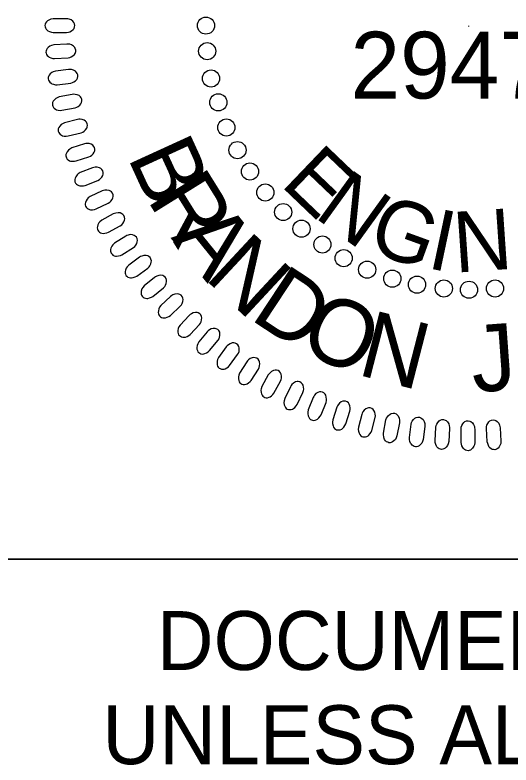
# Model space of a CAD drawing. Extents: x 505602 to 507286, y 483109 to 484209.
# Drawn here: x 507076.9 to 507123.2, y 484026.9 to 484097 of the extents above; entities that cross this region are included whole.
import ezdxf

# ---------------------------------------------------------------- set-up
doc = ezdxf.new("R2010")
doc.units = 0
for name, color, linetype in [('Sheet PE Seal Cell', 7, 'Continuous'), ('Sheet Profile CELL', 7, 'Continuous'), ('Sheet Sticker Exception Certification CELL', 7, 'Continuous')]:
    doc.layers.add(name, color=color, linetype=linetype)

msp = doc.modelspace()

# ---------------------------------------------------------------- linework, layer by layer
at = {"layer": 'Sheet PE Seal Cell'}
msp.add_line((507119.206, 484095.991), (507119.206, 484095.944), dxfattribs=at)
for points in [[(507081.659, 484096.654), (507080.432, 484096.654), (507080.213, 484096.616), (507080.073, 484096.565), (507079.904, 484096.453), (507079.794, 484096.355), (507079.714, 484096.243), (507079.674, 484096.139), (507079.654, 484096.026), (507079.674, 484095.915), (507079.704, 484095.795), (507079.763, 484095.69), (507079.864, 484095.586), (507079.943, 484095.526), (507080.093, 484095.458), (507080.273, 484095.399), (507080.432, 484095.376), (507081.689, 484095.368), (507081.858, 484095.39), (507081.998, 484095.436), (507082.157, 484095.525), (507082.297, 484095.637), (507082.377, 484095.734), (507082.437, 484095.891), (507082.457, 484096.041), (507082.416, 484096.19), (507082.367, 484096.295), (507082.268, 484096.422), (507082.098, 484096.542), (507081.918, 484096.609), (507081.789, 484096.639)], [(507081.712, 484094.296), (507080.487, 484094.22), (507080.271, 484094.169), (507080.134, 484094.108), (507079.972, 484093.985), (507079.868, 484093.881), (507079.796, 484093.764), (507079.763, 484093.658), (507079.75, 484093.544), (507079.777, 484093.434), (507079.815, 484093.316), (507079.88, 484093.216), (507079.987, 484093.117), (507080.07, 484093.063), (507080.223, 484093.005), (507080.406, 484092.956), (507080.566, 484092.944), (507081.822, 484093.015), (507081.99, 484093.048), (507082.126, 484093.102), (507082.279, 484093.202), (507082.412, 484093.322), (507082.486, 484093.423), (507082.536, 484093.584), (507082.546, 484093.734), (507082.497, 484093.881), (507082.44, 484093.983), (507082.333, 484094.103), (507082.157, 484094.212), (507081.973, 484094.268), (507081.842, 484094.29)], [(507081.876, 484091.915), (507080.659, 484091.762), (507080.446, 484091.697), (507080.314, 484091.628), (507080.16, 484091.496), (507080.063, 484091.385), (507079.998, 484091.264), (507079.972, 484091.155), (507079.966, 484091.041), (507080, 484090.933), (507080.044, 484090.818), (507080.116, 484090.721), (507080.229, 484090.63), (507080.316, 484090.581), (507080.472, 484090.533), (507080.658, 484090.496), (507080.819, 484090.494), (507082.067, 484090.643), (507082.232, 484090.686), (507082.365, 484090.749), (507082.512, 484090.857), (507082.636, 484090.986), (507082.704, 484091.092), (507082.743, 484091.256), (507082.744, 484091.407), (507082.686, 484091.55), (507082.623, 484091.648), (507082.509, 484091.762), (507082.326, 484091.859), (507082.139, 484091.903), (507082.007, 484091.916)], [(507082.21, 484089.59), (507081.004, 484089.36), (507080.796, 484089.282), (507080.669, 484089.206), (507080.523, 484089.063), (507080.433, 484088.947), (507080.376, 484088.822), (507080.356, 484088.712), (507080.358, 484088.598), (507080.398, 484088.492), (507080.45, 484088.38), (507080.528, 484088.288), (507080.646, 484088.204), (507080.735, 484088.16), (507080.895, 484088.122), (507081.083, 484088.097), (507081.243, 484088.104), (507082.479, 484088.332), (507082.642, 484088.386), (507082.771, 484088.456), (507082.91, 484088.574), (507083.027, 484088.711), (507083.087, 484088.821), (507083.116, 484088.986), (507083.108, 484089.137), (507083.041, 484089.276), (507082.972, 484089.37), (507082.85, 484089.476), (507082.662, 484089.561), (507082.472, 484089.594), (507082.34, 484089.599)], [(507082.689, 484087.249), (507081.501, 484086.944), (507081.298, 484086.853), (507081.175, 484086.768), (507081.039, 484086.617), (507080.957, 484086.496), (507080.907, 484086.367), (507080.895, 484086.256), (507080.903, 484086.142), (507080.95, 484086.039), (507081.009, 484085.931), (507081.093, 484085.844), (507081.216, 484085.767), (507081.308, 484085.729), (507081.469, 484085.701), (507081.658, 484085.688), (507081.818, 484085.706), (507083.037, 484086.01), (507083.196, 484086.074), (507083.32, 484086.153), (507083.452, 484086.279), (507083.56, 484086.422), (507083.613, 484086.536), (507083.632, 484086.703), (507083.614, 484086.853), (507083.538, 484086.988), (507083.464, 484087.077), (507083.336, 484087.176), (507083.142, 484087.249), (507082.951, 484087.27), (507082.818, 484087.266)], [(507083.343, 484084.965), (507082.176, 484084.586), (507081.979, 484084.483), (507081.862, 484084.391), (507081.735, 484084.231), (507081.661, 484084.104), (507081.62, 484083.973), (507081.615, 484083.862), (507081.63, 484083.749), (507081.684, 484083.649), (507081.749, 484083.544), (507081.838, 484083.463), (507081.966, 484083.395), (507082.059, 484083.361), (507082.223, 484083.344), (507082.412, 484083.343), (507082.571, 484083.37), (507083.768, 484083.751), (507083.922, 484083.825), (507084.042, 484083.911), (507084.165, 484084.045), (507084.263, 484084.195), (507084.31, 484084.312), (507084.318, 484084.48), (507084.291, 484084.628), (507084.207, 484084.758), (507084.127, 484084.842), (507083.993, 484084.932), (507083.795, 484084.994), (507083.603, 484085.002), (507083.471, 484084.99)], [(507084.102, 484082.727), (507082.961, 484082.277), (507082.77, 484082.161), (507082.659, 484082.061), (507082.543, 484081.894), (507082.477, 484081.763), (507082.444, 484081.63), (507082.446, 484081.518), (507082.468, 484081.406), (507082.528, 484081.31), (507082.6, 484081.209), (507082.693, 484081.134), (507082.825, 484081.074), (507082.921, 484081.047), (507083.086, 484081.04), (507083.274, 484081.05), (507083.431, 484081.088), (507084.602, 484081.543), (507084.752, 484081.626), (507084.865, 484081.719), (507084.98, 484081.861), (507085.069, 484082.017), (507085.108, 484082.137), (507085.105, 484082.305), (507085.069, 484082.452), (507084.977, 484082.575), (507084.892, 484082.654), (507084.753, 484082.736), (507084.551, 484082.784), (507084.359, 484082.781), (507084.228, 484082.761)], [(507085.001, 484080.568), (507083.891, 484080.046), (507083.709, 484079.919), (507083.604, 484079.812), (507083.499, 484079.638), (507083.441, 484079.504), (507083.416, 484079.368), (507083.425, 484079.257), (507083.454, 484079.147), (507083.52, 484079.054), (507083.598, 484078.958), (507083.697, 484078.889), (507083.832, 484078.837), (507083.929, 484078.817), (507084.093, 484078.819), (507084.281, 484078.842), (507084.435, 484078.889), (507085.576, 484079.417), (507085.719, 484079.51), (507085.827, 484079.61), (507085.932, 484079.758), (507086.012, 484079.919), (507086.043, 484080.042), (507086.03, 484080.209), (507085.984, 484080.353), (507085.884, 484080.471), (507085.794, 484080.545), (507085.651, 484080.618), (507085.446, 484080.653), (507085.255, 484080.638), (507085.125, 484080.61)], [(507086.049, 484078.419), (507084.973, 484077.829), (507084.799, 484077.691), (507084.702, 484077.577), (507084.607, 484077.398), (507084.558, 484077.259), (507084.542, 484077.123), (507084.557, 484077.012), (507084.594, 484076.904), (507084.666, 484076.816), (507084.75, 484076.725), (507084.852, 484076.662), (507084.99, 484076.619), (507085.089, 484076.604), (507085.252, 484076.617), (507085.438, 484076.652), (507085.589, 484076.708), (507086.694, 484077.307), (507086.832, 484077.409), (507086.932, 484077.515), (507087.029, 484077.67), (507087.097, 484077.835), (507087.121, 484077.96), (507087.097, 484078.126), (507087.043, 484078.267), (507086.936, 484078.378), (507086.842, 484078.446), (507086.693, 484078.509), (507086.487, 484078.532), (507086.297, 484078.505), (507086.169, 484078.469)], [(507087.205, 484076.345), (507086.169, 484075.687), (507086.003, 484075.539), (507085.914, 484075.42), (507085.83, 484075.234), (507085.79, 484075.094), (507085.783, 484074.956), (507085.805, 484074.846), (507085.848, 484074.741), (507085.926, 484074.657), (507086.015, 484074.572), (507086.121, 484074.516), (507086.261, 484074.481), (507086.36, 484074.473), (507086.523, 484074.496), (507086.707, 484074.542), (507086.853, 484074.608), (507087.919, 484075.275), (507088.05, 484075.384), (507088.144, 484075.498), (507088.23, 484075.658), (507088.288, 484075.828), (507088.304, 484075.953), (507088.27, 484076.118), (507088.207, 484076.255), (507088.093, 484076.359), (507087.995, 484076.421), (507087.842, 484076.475), (507087.635, 484076.485), (507087.447, 484076.446), (507087.322, 484076.401)], [(507088.482, 484074.37), (507087.488, 484073.649), (507087.333, 484073.49), (507087.25, 484073.366), (507087.179, 484073.175), (507087.148, 484073.032), (507087.149, 484072.894), (507087.178, 484072.787), (507087.228, 484072.683), (507087.31, 484072.605), (507087.405, 484072.526), (507087.515, 484072.476), (507087.657, 484072.45), (507087.756, 484072.449), (507087.917, 484072.482), (507088.097, 484072.539), (507088.24, 484072.614), (507089.261, 484073.347), (507089.385, 484073.465), (507089.471, 484073.583), (507089.548, 484073.749), (507089.595, 484073.922), (507089.603, 484074.047), (507089.559, 484074.21), (507089.487, 484074.343), (507089.367, 484074.44), (507089.265, 484074.495), (507089.11, 484074.54), (507088.903, 484074.537), (507088.717, 484074.486), (507088.595, 484074.434)], [(507089.885, 484072.488), (507088.939, 484071.706), (507088.794, 484071.538), (507088.72, 484071.409), (507088.661, 484071.215), (507088.638, 484071.07), (507088.648, 484070.933), (507088.684, 484070.827), (507088.74, 484070.727), (507088.827, 484070.654), (507088.926, 484070.581), (507089.039, 484070.538), (507089.182, 484070.521), (507089.282, 484070.526), (507089.44, 484070.569), (507089.616, 484070.638), (507089.754, 484070.721), (507090.727, 484071.517), (507090.844, 484071.642), (507090.922, 484071.766), (507090.988, 484071.936), (507091.025, 484072.112), (507091.024, 484072.237), (507090.97, 484072.397), (507090.89, 484072.524), (507090.764, 484072.614), (507090.659, 484072.663), (507090.501, 484072.698), (507090.295, 484072.682), (507090.113, 484072.619), (507089.994, 484072.56)], [(507091.395, 484070.718), (507090.5, 484069.878), (507090.366, 484069.701), (507090.3, 484069.568), (507090.253, 484069.37), (507090.24, 484069.224), (507090.258, 484069.087), (507090.301, 484068.983), (507090.363, 484068.888), (507090.454, 484068.82), (507090.558, 484068.753), (507090.673, 484068.718), (507090.818, 484068.71), (507090.916, 484068.721), (507091.072, 484068.774), (507091.244, 484068.853), (507091.375, 484068.946), (507092.296, 484069.801), (507092.405, 484069.933), (507092.476, 484070.062), (507092.531, 484070.236), (507092.556, 484070.413), (507092.548, 484070.538), (507092.484, 484070.695), (507092.396, 484070.817), (507092.265, 484070.898), (507092.157, 484070.941), (507091.997, 484070.965), (507091.792, 484070.936), (507091.614, 484070.862), (507091.5, 484070.795)], [(507093.131, 484068.94), (507092.29, 484068.045), (507092.167, 484067.86), (507092.11, 484067.723), (507092.075, 484067.522), (507092.071, 484067.375), (507092.098, 484067.241), (507092.147, 484067.141), (507092.215, 484067.049), (507092.31, 484066.987), (507092.419, 484066.927), (507092.535, 484066.898), (507092.68, 484066.9), (507092.778, 484066.916), (507092.93, 484066.979), (507093.096, 484067.069), (507093.222, 484067.17), (507094.088, 484068.081), (507094.187, 484068.22), (507094.25, 484068.353), (507094.294, 484068.53), (507094.308, 484068.708), (507094.292, 484068.833), (507094.219, 484068.984), (507094.123, 484069.102), (507093.987, 484069.174), (507093.876, 484069.21), (507093.716, 484069.225), (507093.513, 484069.182), (507093.34, 484069.098), (507093.23, 484069.024)], [(507094.821, 484067.41), (507094.038, 484066.464), (507093.927, 484066.271), (507093.878, 484066.131), (507093.856, 484065.929), (507093.862, 484065.782), (507093.897, 484065.649), (507093.952, 484065.551), (507094.026, 484065.464), (507094.124, 484065.409), (507094.236, 484065.356), (507094.354, 484065.335), (507094.499, 484065.345), (507094.596, 484065.368), (507094.743, 484065.44), (507094.903, 484065.54), (507095.023, 484065.649), (507095.83, 484066.613), (507095.921, 484066.757), (507095.974, 484066.894), (507096.008, 484067.073), (507096.011, 484067.252), (507095.986, 484067.377), (507095.903, 484067.522), (507095.801, 484067.633), (507095.661, 484067.697), (507095.547, 484067.726), (507095.386, 484067.73), (507095.187, 484067.676), (507095.019, 484067.58), (507094.914, 484067.5)], [(507096.601, 484066.009), (507095.88, 484065.016), (507095.781, 484064.817), (507095.741, 484064.673), (507095.732, 484064.47), (507095.747, 484064.324), (507095.79, 484064.194), (507095.851, 484064.1), (507095.93, 484064.018), (507096.033, 484063.968), (507096.148, 484063.922), (507096.267, 484063.909), (507096.41, 484063.928), (507096.506, 484063.957), (507096.648, 484064.039), (507096.802, 484064.149), (507096.914, 484064.264), (507097.659, 484065.277), (507097.74, 484065.427), (507097.786, 484065.567), (507097.808, 484065.748), (507097.8, 484065.927), (507097.767, 484066.048), (507097.676, 484066.19), (507097.566, 484066.294), (507097.422, 484066.349), (507097.308, 484066.37), (507097.147, 484066.365), (507096.95, 484066.297), (507096.79, 484066.192), (507096.69, 484066.104)], [(507098.503, 484064.596), (507097.846, 484063.56), (507097.759, 484063.355), (507097.728, 484063.209), (507097.732, 484063.005), (507097.756, 484062.861), (507097.808, 484062.734), (507097.874, 484062.643), (507097.959, 484062.567), (507098.063, 484062.523), (507098.181, 484062.484), (507098.301, 484062.479), (507098.443, 484062.507), (507098.536, 484062.543), (507098.673, 484062.632), (507098.82, 484062.752), (507098.924, 484062.875), (507099.604, 484063.931), (507099.676, 484064.087), (507099.713, 484064.229), (507099.723, 484064.411), (507099.703, 484064.589), (507099.663, 484064.709), (507099.564, 484064.844), (507099.448, 484064.94), (507099.3, 484064.987), (507099.185, 484065.001), (507099.025, 484064.985), (507098.833, 484064.906), (507098.679, 484064.79), (507098.585, 484064.697)], [(507100.521, 484063.38), (507099.93, 484062.305), (507099.857, 484062.095), (507099.835, 484061.948), (507099.852, 484061.745), (507099.884, 484061.602), (507099.944, 484061.478), (507100.016, 484061.392), (507100.105, 484061.321), (507100.212, 484061.285), (507100.332, 484061.253), (507100.452, 484061.255), (507100.592, 484061.292), (507100.683, 484061.333), (507100.814, 484061.432), (507100.953, 484061.56), (507101.05, 484061.689), (507101.662, 484062.787), (507101.723, 484062.946), (507101.751, 484063.09), (507101.75, 484063.273), (507101.72, 484063.449), (507101.673, 484063.566), (507101.564, 484063.694), (507101.442, 484063.784), (507101.292, 484063.821), (507101.176, 484063.828), (507101.017, 484063.802), (507100.831, 484063.71), (507100.685, 484063.586), (507100.596, 484063.487)], [(507102.58, 484062.274), (507102.058, 484061.164), (507101.998, 484060.95), (507101.986, 484060.801), (507102.015, 484060.599), (507102.056, 484060.459), (507102.124, 484060.339), (507102.201, 484060.258), (507102.295, 484060.193), (507102.404, 484060.163), (507102.525, 484060.139), (507102.645, 484060.148), (507102.783, 484060.194), (507102.871, 484060.241), (507102.995, 484060.347), (507103.126, 484060.484), (507103.215, 484060.619), (507103.757, 484061.753), (507103.808, 484061.916), (507103.827, 484062.061), (507103.814, 484062.244), (507103.773, 484062.418), (507103.718, 484062.532), (507103.602, 484062.652), (507103.474, 484062.735), (507103.323, 484062.762), (507103.206, 484062.761), (507103.049, 484062.726), (507102.869, 484062.623), (507102.732, 484062.489), (507102.65, 484062.385)], [(507104.708, 484061.266), (507104.256, 484060.125), (507104.21, 484059.907), (507104.207, 484059.758), (507104.249, 484059.559), (507104.298, 484059.421), (507104.374, 484059.306), (507104.456, 484059.23), (507104.553, 484059.17), (507104.664, 484059.148), (507104.787, 484059.132), (507104.906, 484059.148), (507105.04, 484059.203), (507105.125, 484059.255), (507105.243, 484059.369), (507105.364, 484059.514), (507105.444, 484059.654), (507105.914, 484060.82), (507105.956, 484060.985), (507105.965, 484061.131), (507105.941, 484061.313), (507105.888, 484061.484), (507105.827, 484061.594), (507105.703, 484061.708), (507105.571, 484061.781), (507105.418, 484061.799), (507105.302, 484061.791), (507105.147, 484061.746), (507104.974, 484061.632), (507104.845, 484061.489), (507104.77, 484061.38)], [(507106.917, 484060.363), (507106.537, 484059.197), (507106.505, 484058.976), (507106.511, 484058.828), (507106.565, 484058.631), (507106.624, 484058.497), (507106.706, 484058.387), (507106.793, 484058.317), (507106.894, 484058.263), (507107.006, 484058.247), (507107.13, 484058.239), (507107.247, 484058.263), (507107.378, 484058.326), (507107.459, 484058.383), (507107.57, 484058.505), (507107.682, 484058.657), (507107.753, 484058.801), (507108.149, 484059.994), (507108.18, 484060.162), (507108.18, 484060.309), (507108.144, 484060.488), (507108.081, 484060.655), (507108.013, 484060.762), (507107.882, 484060.867), (507107.746, 484060.932), (507107.592, 484060.941), (507107.477, 484060.925), (507107.325, 484060.87), (507107.159, 484060.746), (507107.039, 484060.596), (507106.971, 484060.482)], [(507109.25, 484059.69), (507108.944, 484058.502), (507108.926, 484058.281), (507108.941, 484058.132), (507109.008, 484057.94), (507109.074, 484057.809), (507109.164, 484057.705), (507109.255, 484057.64), (507109.358, 484057.592), (507109.472, 484057.584), (507109.595, 484057.584), (507109.711, 484057.615), (507109.837, 484057.686), (507109.915, 484057.747), (507110.018, 484057.876), (507110.12, 484058.035), (507110.182, 484058.184), (507110.502, 484059.399), (507110.522, 484059.569), (507110.513, 484059.715), (507110.466, 484059.892), (507110.393, 484060.055), (507110.318, 484060.157), (507110.181, 484060.254), (507110.042, 484060.31), (507109.886, 484060.309), (507109.773, 484060.287), (507109.625, 484060.222), (507109.467, 484060.087), (507109.357, 484059.93), (507109.296, 484059.812)], [(507112.772, 484058.903), (507112.541, 484057.698), (507112.463, 484057.489), (507112.386, 484057.362), (507112.244, 484057.216), (507112.128, 484057.127), (507112.003, 484057.07), (507111.892, 484057.05), (507111.778, 484057.052), (507111.673, 484057.092), (507111.56, 484057.144), (507111.469, 484057.222), (507111.385, 484057.34), (507111.341, 484057.43), (507111.303, 484057.589), (507111.278, 484057.777), (507111.286, 484057.938), (507111.514, 484059.173), (507111.568, 484059.336), (507111.639, 484059.464), (507111.757, 484059.604), (507111.893, 484059.72), (507112.003, 484059.781), (507112.168, 484059.81), (507112.32, 484059.801), (507112.458, 484059.734), (507112.552, 484059.665), (507112.658, 484059.544), (507112.743, 484059.355), (507112.776, 484059.165), (507112.781, 484059.033)], [(507115.138, 484058.577), (507114.983, 484057.36), (507114.919, 484057.147), (507114.849, 484057.014), (507114.717, 484056.86), (507114.607, 484056.764), (507114.485, 484056.698), (507114.377, 484056.672), (507114.263, 484056.667), (507114.155, 484056.701), (507114.039, 484056.745), (507113.943, 484056.817), (507113.852, 484056.93), (507113.802, 484057.017), (507113.754, 484057.174), (507113.718, 484057.359), (507113.715, 484057.52), (507113.866, 484058.767), (507113.909, 484058.933), (507113.972, 484059.066), (507114.08, 484059.213), (507114.209, 484059.338), (507114.316, 484059.404), (507114.479, 484059.444), (507114.63, 484059.445), (507114.773, 484059.386), (507114.871, 484059.324), (507114.985, 484059.209), (507115.081, 484059.026), (507115.126, 484058.839), (507115.139, 484058.707)], [(507117.455, 484058.379), (507117.377, 484057.155), (507117.326, 484056.939), (507117.265, 484056.802), (507117.143, 484056.64), (507117.039, 484056.536), (507116.922, 484056.464), (507116.815, 484056.43), (507116.701, 484056.418), (507116.591, 484056.446), (507116.474, 484056.482), (507116.373, 484056.548), (507116.275, 484056.655), (507116.22, 484056.738), (507116.162, 484056.892), (507116.114, 484057.075), (507116.102, 484057.236), (507116.173, 484058.49), (507116.207, 484058.658), (507116.261, 484058.794), (507116.36, 484058.948), (507116.48, 484059.08), (507116.583, 484059.154), (507116.743, 484059.203), (507116.894, 484059.214), (507117.041, 484059.164), (507117.141, 484059.108), (507117.262, 484059.001), (507117.37, 484058.824), (507117.427, 484058.64), (507117.448, 484058.51)], [(507119.808, 484058.307), (507119.808, 484057.08), (507119.77, 484056.862), (507119.718, 484056.721), (507119.606, 484056.552), (507119.508, 484056.442), (507119.396, 484056.362), (507119.292, 484056.323), (507119.18, 484056.303), (507119.068, 484056.323), (507118.948, 484056.353), (507118.843, 484056.412), (507118.738, 484056.513), (507118.679, 484056.592), (507118.611, 484056.742), (507118.552, 484056.921), (507118.529, 484057.081), (507118.522, 484058.337), (507118.545, 484058.507), (507118.59, 484058.647), (507118.679, 484058.806), (507118.791, 484058.946), (507118.889, 484059.026), (507119.046, 484059.085), (507119.196, 484059.105), (507119.345, 484059.065), (507119.45, 484059.015), (507119.577, 484058.916), (507119.696, 484058.746), (507119.764, 484058.566), (507119.793, 484058.437)], [(507122.175, 484058.43), (507122.251, 484057.205), (507122.228, 484056.984), (507122.185, 484056.841), (507122.083, 484056.665), (507121.994, 484056.549), (507121.886, 484056.463), (507121.785, 484056.417), (507121.674, 484056.39), (507121.561, 484056.403), (507121.44, 484056.425), (507121.331, 484056.478), (507121.22, 484056.572), (507121.156, 484056.647), (507121.08, 484056.793), (507121.009, 484056.968), (507120.976, 484057.126), (507120.89, 484058.379), (507120.902, 484058.55), (507120.938, 484058.692), (507121.018, 484058.857), (507121.121, 484059.003), (507121.213, 484059.089), (507121.366, 484059.159), (507121.514, 484059.188), (507121.665, 484059.157), (507121.773, 484059.114), (507121.906, 484059.023), (507122.036, 484058.861), (507122.115, 484058.685), (507122.153, 484058.558)]]:
    msp.add_lwpolyline(points, close=True, dxfattribs=at)
for centre in [(507094.698, 484096.018), (507094.817, 484093.628), (507095.174, 484091.078), (507095.85, 484088.847), (507096.606, 484086.496), (507097.641, 484084.385), (507098.81, 484082.381), (507100.242, 484080.428), (507101.914, 484078.595), (507103.625, 484077.041), (507105.576, 484075.567), (507107.566, 484074.291), (507109.755, 484073.215), (507112.104, 484072.377), (507114.413, 484071.819), (507116.921, 484071.46), (507119.27, 484071.339), (507121.699, 484071.458)]:
    msp.add_circle(centre, 0.801, dxfattribs=at)
at = {"layer": 'Sheet Profile CELL'}
msp.add_lwpolyline([(507069.03, 484158.662), (507169.08, 484158.662), (507169.08, 484046.162), (507069.03, 484046.162)], close=True, dxfattribs=at)
at = {"layer": 'Sheet Sticker Exception Certification CELL'}
msp.add_line((507069.03, 484046.162), (507269.067, 484046.162), dxfattribs=at)
msp.add_line((507069.03, 484046.162), (507269.067, 484046.162), dxfattribs=at)

# ---------------------------------------------------------------- texts
at = {"layer": 'Sheet PE Seal Cell'}
for s, height, rotation, p in [('29470', 6.2363, 359.98136, (507108.193, 484089.206)), ('B', 6.236, 294.5897, (507087.323, 484083.768)), ('E', 5.669, 316.26559, (507101.563, 484081.146)), ('R', 6.236, 301.86473, (507089.134, 484079.811)), ('N', 5.669, 324.20538, (507104.698, 484078.191)), ('G', 5.669, 340.08498, (507109.592, 484075.093)), ('N', 5.669, 3.90437, (507117.974, 484072.931)), ('A', 6.236, 308.98157, (507091.377, 484076.193)), ('I', 5.669, 348.02477, (507115.221, 484073.403)), ('N', 6.236, 317.09274, (507094.456, 484072.445)), ('D', 6.236, 326.58243, (507098.686, 484068.664)), ('O', 6.236, 335.45066, (507103.152, 484065.806)), ('N', 6.236, 345.5505, (507108.704, 484063.434)), ('J', 6.236, 4.1457, (507119.655, 484061.742))]:
    msp.add_text(s, height=height, rotation=rotation, dxfattribs=at).set_placement(p)
at = {"layer": 'Sheet Sticker Exception Certification CELL'}
for s, p in [('DOCUMENT NOT CONSIDERED FINAL', (507090.101, 484035.816)), ('DOCUMENT NOT CONSIDERED FINAL', (507090.101, 484035.816)), ('UNLESS ALL SIGNATURES COMPLETED', (507085.03, 484027.016)), ('UNLESS ALL SIGNATURES COMPLETED', (507085.03, 484027.016))]:
    msp.add_text(s, height=5.5, dxfattribs=at).set_placement(p)

doc.saveas('drawing.dxf')
